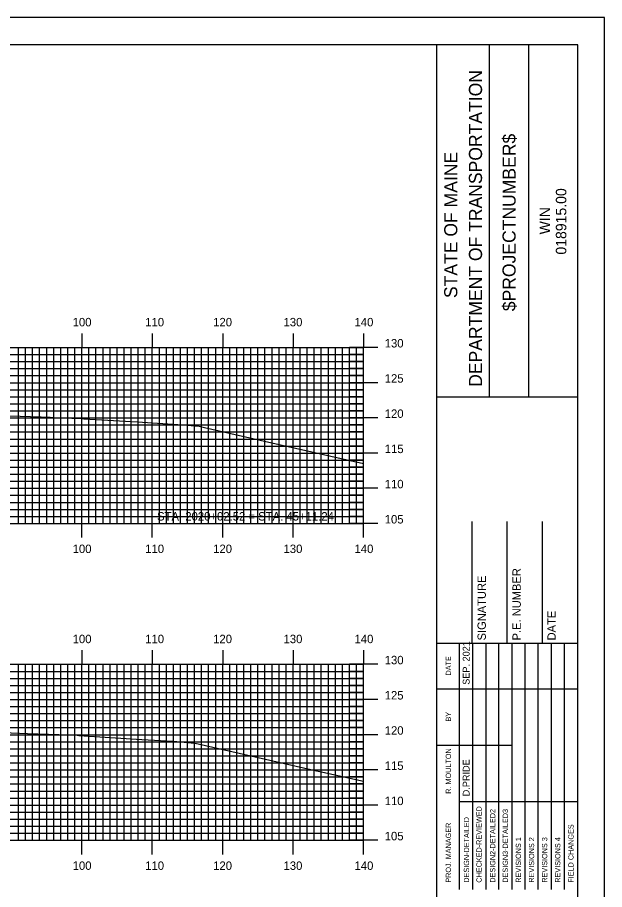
# Model space of a CAD drawing. Extents: x 855468 to 855811, y 366605 to 366825.
# Drawn here: x 855724.4 to 855807.8, y 366701.1 to 366824.9 of the extents above; entities that cross this region are included whole.
import ezdxf

# ---------------------------------------------------------------- set-up
doc = ezdxf.new("R2010")
doc.units = 0
for name, color, linetype in [('BORDER', 7, 'Continuous'), ('D_Drainage_Text', 7, 'Continuous'), ('H_V ANNOTATION', 7, 'Continuous'), ('M_Roadway_Centerline', 7, 'Continuous'), ('MAJOR', 7, 'Continuous'), ('MINOR', 7, 'Continuous'), ('PLOT BOUNDARY', 7, 'Continuous'), ('S_Roadway_Centerline', 7, 'Continuous')]:
    doc.layers.add(name, color=color, linetype=linetype)

msp = doc.modelspace()

# ---------------------------------------------------------------- linework, layer by layer
at = {"layer": 'BORDER'}
for p, q in [((855783.98, 366611.06), (855783.98, 366821.06)), ((855791.44, 366771.05), (855791.44, 366821.05)), ((855797.03, 366771.05), (855797.03, 366821.05)), ((855783.98, 366771.04), (855803.98, 366771.04)), ((855788.98, 366736.06), (855788.98, 366753.36)), ((855793.98, 366736.06), (855793.98, 366753.36)), ((855798.98, 366736.06), (855798.98, 366753.36)), ((855783.98, 366736.06), (855803.98, 366736.06))]:
    msp.add_line(p, q, dxfattribs=at)
msp.add_lwpolyline([(855483.98, 366611.06), (855803.98, 366611.06), (855803.98, 366821.06), (855483.98, 366821.06)], close=True, dxfattribs=at)
for points in [[(855787.21, 366729.56), (855787.21, 366736.06)], [(855789.08, 366701.07), (855789.08, 366736.06)], [(855790.94, 366736.06), (855790.94, 366701.07)], [(855792.8, 366701.07), (855792.8, 366736.06)], [(855794.67, 366701.07), (855794.67, 366736.06)], [(855796.53, 366701.07), (855796.53, 366736.06)], [(855798.39, 366701.07), (855798.39, 366736.06)], [(855800.26, 366701.07), (855800.26, 366736.06)], [(855802.12, 366701.07), (855802.12, 366736.06)], [(855787.21, 366701.07), (855787.21, 366734.65)], [(855783.98, 366729.56), (855803.98, 366729.56)], [(855783.98, 366721.56), (855787.21, 366721.56)], [(855787.21, 366721.56), (855794.67, 366721.56)], [(855787.21, 366713.56), (855803.98, 366713.56)]]:
    msp.add_lwpolyline(points, dxfattribs=at)
at = {"layer": 'MAJOR'}
for p, q in [((855733.58, 366780.06), (855733.58, 366778.06)), ((855743.58, 366780.06), (855743.58, 366778.06)), ((855753.58, 366780.06), (855753.58, 366778.06)), ((855763.58, 366780.06), (855763.58, 366778.06)), ((855773.58, 366780.06), (855773.58, 366778.06)), ((855493.58, 366778.06), (855773.58, 366778.06)), ((855493.58, 366778.06), (855773.58, 366778.06)), ((855733.58, 366753.06), (855733.58, 366778.06)), ((855743.58, 366753.06), (855743.58, 366778.06)), ((855753.58, 366753.06), (855753.58, 366778.06)), ((855763.58, 366753.06), (855763.58, 366778.06)), ((855775.59, 366778.06), (855771.58, 366778.06)), ((855773.58, 366753.06), (855773.58, 366778.06)), ((855773.58, 366753.06), (855773.58, 366778.06)), ((855493.58, 366773.06), (855773.58, 366773.06)), ((855775.59, 366773.06), (855771.58, 366773.06)), ((855493.58, 366768.06), (855773.58, 366768.06)), ((855775.59, 366768.06), (855771.58, 366768.06)), ((855493.58, 366763.06), (855773.58, 366763.06)), ((855775.59, 366763.06), (855771.58, 366763.06)), ((855493.58, 366758.06), (855773.58, 366758.06)), ((855775.59, 366758.06), (855771.58, 366758.06)), ((855493.58, 366753.06), (855773.58, 366753.06)), ((855493.58, 366753.06), (855773.58, 366753.06)), ((855733.58, 366751.05), (855733.58, 366753.06)), ((855743.58, 366751.05), (855743.58, 366753.06)), ((855753.58, 366751.05), (855753.58, 366753.06)), ((855763.58, 366751.05), (855763.58, 366753.06)), ((855775.59, 366753.06), (855771.58, 366753.06)), ((855773.58, 366751.05), (855773.58, 366753.06)), ((855733.58, 366735.06), (855733.58, 366733.06)), ((855743.58, 366735.06), (855743.58, 366733.06)), ((855753.58, 366735.06), (855753.58, 366733.06)), ((855763.58, 366735.06), (855763.58, 366733.06)), ((855773.58, 366735.06), (855773.58, 366733.06)), ((855493.58, 366733.06), (855773.58, 366733.06)), ((855493.58, 366733.06), (855773.58, 366733.06)), ((855733.58, 366708.06), (855733.58, 366733.06)), ((855743.58, 366708.06), (855743.58, 366733.06)), ((855753.58, 366708.06), (855753.58, 366733.06)), ((855763.58, 366708.06), (855763.58, 366733.06)), ((855775.59, 366733.06), (855771.58, 366733.06)), ((855773.58, 366708.06), (855773.58, 366733.06)), ((855773.58, 366708.06), (855773.58, 366733.06)), ((855493.58, 366728.06), (855773.58, 366728.06)), ((855775.59, 366728.06), (855771.58, 366728.06)), ((855493.58, 366723.06), (855773.58, 366723.06)), ((855775.59, 366723.06), (855771.58, 366723.06)), ((855493.58, 366718.06), (855773.58, 366718.06)), ((855775.59, 366718.06), (855771.58, 366718.06)), ((855493.58, 366713.06), (855773.58, 366713.06)), ((855775.59, 366713.06), (855771.58, 366713.06)), ((855493.58, 366708.06), (855773.58, 366708.06)), ((855493.58, 366708.06), (855773.58, 366708.06)), ((855733.58, 366706.05), (855733.58, 366708.06)), ((855743.58, 366706.05), (855743.58, 366708.06)), ((855753.58, 366706.05), (855753.58, 366708.06)), ((855763.58, 366706.05), (855763.58, 366708.06)), ((855775.59, 366708.06), (855771.58, 366708.06)), ((855773.58, 366706.05), (855773.58, 366708.06))]:
    msp.add_line(p, q, dxfattribs=at)
at = {"layer": 'MINOR'}
for p, q in [((855724.58, 366753.06), (855724.58, 366778.06)), ((855725.58, 366753.06), (855725.58, 366778.06)), ((855726.58, 366753.06), (855726.58, 366778.06)), ((855727.58, 366753.06), (855727.58, 366778.06)), ((855728.58, 366753.06), (855728.58, 366778.06)), ((855729.58, 366753.06), (855729.58, 366778.06)), ((855730.58, 366753.06), (855730.58, 366778.06)), ((855731.58, 366753.06), (855731.58, 366778.06)), ((855732.58, 366753.06), (855732.58, 366778.06)), ((855734.58, 366753.06), (855734.58, 366778.06)), ((855735.58, 366753.06), (855735.58, 366778.06)), ((855736.58, 366753.06), (855736.58, 366778.06)), ((855737.58, 366753.06), (855737.58, 366778.06)), ((855738.58, 366753.06), (855738.58, 366778.06)), ((855739.58, 366753.06), (855739.58, 366778.06)), ((855740.58, 366753.06), (855740.58, 366778.06)), ((855741.58, 366753.06), (855741.58, 366778.06)), ((855742.58, 366753.06), (855742.58, 366778.06)), ((855744.58, 366753.06), (855744.58, 366778.06)), ((855745.58, 366753.06), (855745.58, 366778.06)), ((855746.58, 366753.06), (855746.58, 366778.06)), ((855747.58, 366753.06), (855747.58, 366778.06)), ((855748.58, 366753.06), (855748.58, 366778.06)), ((855749.58, 366753.06), (855749.58, 366778.06)), ((855750.58, 366753.06), (855750.58, 366778.06)), ((855751.58, 366753.06), (855751.58, 366778.06)), ((855752.58, 366753.06), (855752.58, 366778.06)), ((855754.58, 366753.06), (855754.58, 366778.06)), ((855755.58, 366753.06), (855755.58, 366778.06)), ((855756.58, 366753.06), (855756.58, 366778.06)), ((855757.58, 366753.06), (855757.58, 366778.06)), ((855758.58, 366753.06), (855758.58, 366778.06)), ((855759.58, 366753.06), (855759.58, 366778.06)), ((855760.58, 366753.06), (855760.58, 366778.06)), ((855761.58, 366753.06), (855761.58, 366778.06)), ((855762.58, 366753.06), (855762.58, 366778.06)), ((855764.58, 366753.06), (855764.58, 366778.06)), ((855765.58, 366753.06), (855765.58, 366778.06)), ((855766.58, 366753.06), (855766.58, 366778.06)), ((855767.58, 366753.06), (855767.58, 366778.06)), ((855768.58, 366753.06), (855768.58, 366778.06)), ((855769.58, 366753.06), (855769.58, 366778.06)), ((855770.58, 366753.06), (855770.58, 366778.06)), ((855771.58, 366753.06), (855771.58, 366778.06)), ((855772.58, 366753.06), (855772.58, 366778.06)), ((855493.58, 366777.06), (855773.58, 366777.06)), ((855773.58, 366777.06), (855771.58, 366777.06)), ((855493.58, 366776.06), (855773.58, 366776.06)), ((855493.58, 366775.06), (855773.58, 366775.06)), ((855773.58, 366776.06), (855771.58, 366776.06)), ((855773.58, 366775.06), (855771.58, 366775.06)), ((855493.58, 366774.06), (855773.58, 366774.06)), ((855773.58, 366774.06), (855771.58, 366774.06)), ((855493.58, 366772.06), (855773.58, 366772.06)), ((855773.58, 366772.06), (855771.58, 366772.06)), ((855493.58, 366771.06), (855773.58, 366771.06)), ((855493.58, 366770.06), (855773.58, 366770.06)), ((855773.58, 366771.06), (855771.58, 366771.06)), ((855773.58, 366770.06), (855771.58, 366770.06)), ((855493.58, 366769.06), (855773.58, 366769.06)), ((855773.58, 366769.06), (855771.58, 366769.06)), ((855493.58, 366767.06), (855773.58, 366767.06)), ((855773.58, 366767.06), (855771.58, 366767.06)), ((855493.58, 366766.06), (855773.58, 366766.06)), ((855773.58, 366766.06), (855771.58, 366766.06)), ((855493.58, 366765.06), (855773.58, 366765.06)), ((855493.58, 366764.06), (855773.58, 366764.06)), ((855773.58, 366765.06), (855771.58, 366765.06)), ((855773.58, 366764.06), (855771.58, 366764.06)), ((855493.58, 366762.06), (855773.58, 366762.06)), ((855773.58, 366762.06), (855771.58, 366762.06)), ((855493.58, 366761.06), (855773.58, 366761.06)), ((855773.58, 366761.06), (855771.58, 366761.06)), ((855493.58, 366760.06), (855773.58, 366760.06)), ((855493.58, 366759.06), (855773.58, 366759.06)), ((855773.58, 366760.06), (855771.58, 366760.06)), ((855773.58, 366759.06), (855771.58, 366759.06)), ((855493.58, 366757.06), (855773.58, 366757.06)), ((855773.58, 366757.06), (855771.58, 366757.06)), ((855493.58, 366756.06), (855773.58, 366756.06)), ((855773.58, 366756.06), (855771.58, 366756.06)), ((855493.58, 366755.06), (855773.58, 366755.06)), ((855493.58, 366754.06), (855773.58, 366754.06)), ((855773.58, 366755.06), (855771.58, 366755.06)), ((855773.58, 366754.06), (855771.58, 366754.06)), ((855724.58, 366708.06), (855724.58, 366733.06)), ((855725.58, 366708.06), (855725.58, 366733.06)), ((855726.58, 366708.06), (855726.58, 366733.06)), ((855727.58, 366708.06), (855727.58, 366733.06)), ((855728.58, 366708.06), (855728.58, 366733.06)), ((855729.58, 366708.06), (855729.58, 366733.06)), ((855730.58, 366708.06), (855730.58, 366733.06)), ((855731.58, 366708.06), (855731.58, 366733.06)), ((855732.58, 366708.06), (855732.58, 366733.06)), ((855734.58, 366708.06), (855734.58, 366733.06)), ((855735.58, 366708.06), (855735.58, 366733.06)), ((855736.58, 366708.06), (855736.58, 366733.06)), ((855737.58, 366708.06), (855737.58, 366733.06)), ((855738.58, 366708.06), (855738.58, 366733.06)), ((855739.58, 366708.06), (855739.58, 366733.06)), ((855740.58, 366708.06), (855740.58, 366733.06)), ((855741.58, 366708.06), (855741.58, 366733.06)), ((855742.58, 366708.06), (855742.58, 366733.06)), ((855744.58, 366708.06), (855744.58, 366733.06)), ((855745.58, 366708.06), (855745.58, 366733.06)), ((855746.58, 366708.06), (855746.58, 366733.06)), ((855747.58, 366708.06), (855747.58, 366733.06)), ((855748.58, 366708.06), (855748.58, 366733.06)), ((855749.58, 366708.06), (855749.58, 366733.06)), ((855750.58, 366708.06), (855750.58, 366733.06)), ((855751.58, 366708.06), (855751.58, 366733.06)), ((855752.58, 366708.06), (855752.58, 366733.06)), ((855754.58, 366708.06), (855754.58, 366733.06)), ((855755.58, 366708.06), (855755.58, 366733.06)), ((855756.58, 366708.06), (855756.58, 366733.06)), ((855757.58, 366708.06), (855757.58, 366733.06)), ((855758.58, 366708.06), (855758.58, 366733.06)), ((855759.58, 366708.06), (855759.58, 366733.06)), ((855760.58, 366708.06), (855760.58, 366733.06)), ((855761.58, 366708.06), (855761.58, 366733.06)), ((855762.58, 366708.06), (855762.58, 366733.06)), ((855764.58, 366708.06), (855764.58, 366733.06)), ((855765.58, 366708.06), (855765.58, 366733.06)), ((855766.58, 366708.06), (855766.58, 366733.06)), ((855767.58, 366708.06), (855767.58, 366733.06)), ((855768.58, 366708.06), (855768.58, 366733.06)), ((855769.58, 366708.06), (855769.58, 366733.06)), ((855770.58, 366708.06), (855770.58, 366733.06)), ((855771.58, 366708.06), (855771.58, 366733.06)), ((855772.58, 366708.06), (855772.58, 366733.06)), ((855493.58, 366732.06), (855773.58, 366732.06)), ((855773.58, 366732.06), (855771.58, 366732.06)), ((855493.58, 366731.06), (855773.58, 366731.06)), ((855773.58, 366731.06), (855771.58, 366731.06)), ((855493.58, 366730.06), (855773.58, 366730.06)), ((855773.58, 366730.06), (855771.58, 366730.06)), ((855493.58, 366729.06), (855773.58, 366729.06)), ((855773.58, 366729.06), (855771.58, 366729.06)), ((855493.58, 366727.06), (855773.58, 366727.06)), ((855773.58, 366727.06), (855771.58, 366727.06)), ((855493.58, 366726.06), (855773.58, 366726.06)), ((855773.58, 366726.06), (855771.58, 366726.06)), ((855493.58, 366725.06), (855773.58, 366725.06)), ((855773.58, 366725.06), (855771.58, 366725.06)), ((855493.58, 366724.06), (855773.58, 366724.06)), ((855773.58, 366724.06), (855771.58, 366724.06)), ((855493.58, 366722.06), (855773.58, 366722.06)), ((855773.58, 366722.06), (855771.58, 366722.06)), ((855493.58, 366721.06), (855773.58, 366721.06)), ((855773.58, 366721.06), (855771.58, 366721.06)), ((855493.58, 366720.06), (855773.58, 366720.06)), ((855773.58, 366720.06), (855771.58, 366720.06)), ((855493.58, 366719.06), (855773.58, 366719.06)), ((855773.58, 366719.06), (855771.58, 366719.06)), ((855493.58, 366717.06), (855773.58, 366717.06)), ((855773.58, 366717.06), (855771.58, 366717.06)), ((855493.58, 366716.06), (855773.58, 366716.06)), ((855773.58, 366716.06), (855771.58, 366716.06)), ((855493.58, 366715.06), (855773.58, 366715.06)), ((855773.58, 366715.06), (855771.58, 366715.06)), ((855493.58, 366714.06), (855773.58, 366714.06)), ((855773.58, 366714.06), (855771.58, 366714.06)), ((855493.58, 366712.06), (855773.58, 366712.06)), ((855773.58, 366712.06), (855771.58, 366712.06)), ((855493.58, 366711.06), (855773.58, 366711.06)), ((855773.58, 366711.06), (855771.58, 366711.06)), ((855493.58, 366710.06), (855773.58, 366710.06)), ((855773.58, 366710.06), (855771.58, 366710.06)), ((855493.58, 366709.06), (855773.58, 366709.06)), ((855773.58, 366709.06), (855771.58, 366709.06))]:
    msp.add_line(p, q, dxfattribs=at)
at = {"layer": 'PLOT BOUNDARY'}
msp.add_lwpolyline([(855467.8, 366604.94), (855807.8, 366604.94), (855807.8, 366824.94), (855467.8, 366824.94)], close=True, dxfattribs=at)
at = {"layer": 'S_Roadway_Centerline'}
for points in [[(855720.29, 366768.46), (855727.82, 366768.19), (855729.08, 366768.15), (855729.51, 366768.13), (855733.48, 366767.99), (855733.86, 366767.94), (855741.47, 366767.48), (855747.9, 366767.08), (855750.23, 366766.9), (855750.97, 366766.68), (855761.58, 366764.26), (855766.25, 366763.25), (855768.91, 366762.6), (855773.58, 366761.6)], [(855720.05, 366723.45), (855725.85, 366723.24), (855730.29, 366723.07), (855732.89, 366722.98), (855733.13, 366722.95), (855742.11, 366722.39), (855746.55, 366722.12), (855749.63, 366721.88), (855750.08, 366721.74), (855766.07, 366718.11), (855766.91, 366717.92), (855767.39, 366717.81), (855773.58, 366716.48)]]:
    msp.add_lwpolyline(points, dxfattribs=at)

# ---------------------------------------------------------------- texts
at = {"layer": 'BORDER'}
for s, height, p in [('DEPARTMENT OF TRANSPORTATION', 1.8635, (855790.4, 366772.47)), ('$PROJECTNUMBER$', 1.8635, (855795.17, 366783.21)), ('STATE OF MAINE', 1.8635, (855786.89, 366785.08)), ('018915.00', 1.491, (855802.37, 366791.25)), ('WIN', 1.491, (855800.06, 366794.12)), ('P.E. NUMBER', 1.1811, (855795.9, 366736.45)), ('SIGNATURE', 1.181, (855790.94, 366736.45)), ('DATE', 1.181, (855800.86, 366736.45)), ('SEP. 2021', 0.969, (855788.63, 366730.15)), ('DATE', 0.743, (855785.99, 366731.47)), ('BY', 0.743, (855785.99, 366724.93)), ('R. MOULTON', 0.745, (855785.99, 366714.67)), ('D.PRIDE', 0.969, (855788.63, 366714.31)), ('CHECKED-REVIEWED', 0.7455, (855790.34, 366702.04)), ('DESIGN2-DETAILED2', 0.7455, (855792.28, 366702.04)), ('DESIGN3-DETAILED3', 0.7455, (855794.07, 366702.04)), ('DESIGN-DETAILED', 0.7455, (855788.56, 366702.04)), ('PROJ. MANAGER', 0.7455, (855785.99, 366702.04)), ('FIELD CHANGES', 0.7455, (855803.39, 366702.04)), ('REVISIONS 1', 0.7455, (855795.93, 366702.04)), ('REVISIONS 2', 0.7455, (855797.8, 366702.04)), ('REVISIONS 3', 0.7455, (855799.66, 366702.04)), ('REVISIONS 4', 0.7455, (855801.52, 366702.04))]:
    msp.add_text(s, height=height, rotation=90, dxfattribs=at).set_placement(p)
at = {"layer": 'D_Drainage_Text'}
msp.add_text('STA. 2020+02.52 = STA. 45+11.24', height=1.2, dxfattribs=at).set_placement((855744.25, 366753.48))
at = {"layer": 'H_V ANNOTATION'}
for s, p in [('100', (855732.27, 366781.06)), ('110', (855742.57, 366781.06)), ('120', (855752.22, 366781.06)), ('130', (855762.21, 366781.06)), ('140', (855772.29, 366781.06)), ('130', (855776.58, 366778.06)), ('125', (855776.58, 366773.06)), ('120', (855776.58, 366768.06)), ('115', (855776.58, 366763.06)), ('110', (855776.58, 366758.06)), ('105', (855776.58, 366753.06)), ('100', (855732.27, 366748.86)), ('110', (855742.57, 366748.86)), ('120', (855752.22, 366748.86)), ('130', (855762.21, 366748.86)), ('140', (855772.29, 366748.86)), ('100', (855732.27, 366736.06)), ('110', (855742.57, 366736.06)), ('120', (855752.22, 366736.06)), ('130', (855762.21, 366736.06)), ('140', (855772.29, 366736.06)), ('130', (855776.58, 366733.06)), ('125', (855776.58, 366728.06)), ('120', (855776.58, 366723.06)), ('115', (855776.58, 366718.06)), ('110', (855776.58, 366713.06)), ('105', (855776.58, 366708.06)), ('100', (855732.27, 366703.86)), ('110', (855742.57, 366703.86)), ('120', (855752.22, 366703.86)), ('130', (855762.21, 366703.86)), ('140', (855772.29, 366703.86))]:
    msp.add_text(s, height=1.2, dxfattribs=at).set_placement(p)
at = {"layer": 'M_Roadway_Centerline'}
for s, p in [('C', (855733.47, 366767.99)), ('L', (855733.48, 366767.99)), ('C', (855732.88, 366722.98)), ('L', (855732.89, 366722.97))]:
    msp.add_text(s, height=0.0146, dxfattribs=at).set_placement(p)

doc.saveas('drawing.dxf')
